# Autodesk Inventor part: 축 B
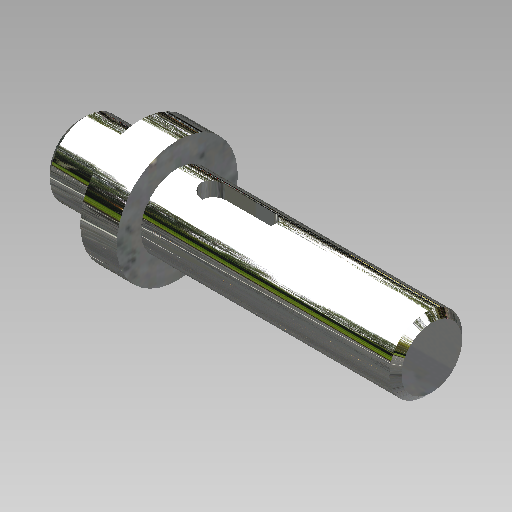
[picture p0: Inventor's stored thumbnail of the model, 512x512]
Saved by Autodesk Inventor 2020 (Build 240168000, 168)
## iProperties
Created: 2020-04
Part Number: 축 B
Material: 알루미늄 6061
Document SubType Name: Modeling
Designer: mduedu
Density: 2.7 g/cm^3
Mass: 20.5879 g
Surface Area: 29.7709 cm^2
Volume: 7.62514 cm^3
Appearance: 알루미늄 - 평지
Author: mduedu
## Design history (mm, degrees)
revolve "회전1" stored, may be unused: angle "d11" = 90 deg
sketch "스케치3"
  geometry: L1 (0, -6)-(0, 6) reference; L2 (0, 6)-(10, 6) reference; L3 (10, 6)-(10, 10) reference; L4 (10, 10)-(16, 10) reference; L5 (16, 10)-(16, 6) reference; L6 (16, 6)-(58, 6) reference; L7 (58, 6)-(58, -6) reference; L8 (58, -6)-(16, -6) reference; L9 (16, -6)-(16, -10) reference; L10 (16, -10)-(10, -10) reference; L11 (10, -10)-(10, -6) reference; L12 (10, -6)-(0, -6) reference; L13 (20, 6)-(32, 6); L14 (32, 6)-(32, 3.5); L15 (32, 3.5)-(20, 3.5); L16 (20, 3.5)-(20, 6); 1 further point
  constraints: 8 end point, 2 parallel, 1 horizontal, 1 perpendicular, 1 point on line
  dimensions: "d17" = 12 distance of L14.end L15.end; "d18" = 2.5 distance of L13.end L14.end; "d19" = 4 distance from line of L16 L4.end
extrude "돌출2" cut sketch "스케치3" stored distance "d20" = 4; taper "d21" = 0 deg
fillet "모깎기2" dims "d22" = 2
chamfer "모따기1" distance "d23" = 1; stored, may be unused: second distance "d24" = 2, angle "d25" = 45 deg
chamfer "모따기2" distance "d26" = 1; stored, may be unused: second distance "d27" = 2, angle "d28" = 45 deg
fillet "모깎기3" dims "d29" = 0.3
node "솔리드1"
sketch "스케치1"
  geometry: L1 (0, 0)-(10, 0); L2 (10, 0)-(10, 6); L3 (10, 6)-(0, 6); L4 (0, 6)-(0, 0); L5 (10, 0)-(16, 0); L6 (16, 0)-(16, 10); L7 (16, 10)-(10, 10); L8 (10, 10)-(10, 0); L9 (16, 0)-(58, 0); L10 (58, 0)-(58, 6); L11 (58, 6)-(16, 6); L12 (16, 6)-(16, 0); L13 (58, 0)-(58, 0); L14 (58, 5)-(58, 0)
  constraints: 28 end point, 6 parallel, 4 horizontal, 3 perpendicular
  dimensions: "d2" = 10 distance of L2.end L3.end; "d3" = 6 distance of L6.end L7.end; "d7" = 12 diameter of L11 L9; "d8" = 12 diameter of L3 L1; "d9" = 20 diameter of L7 L5; "d36" = 58 distance between parallel lines of L10 L4
node "절단 모서리 투영2"
